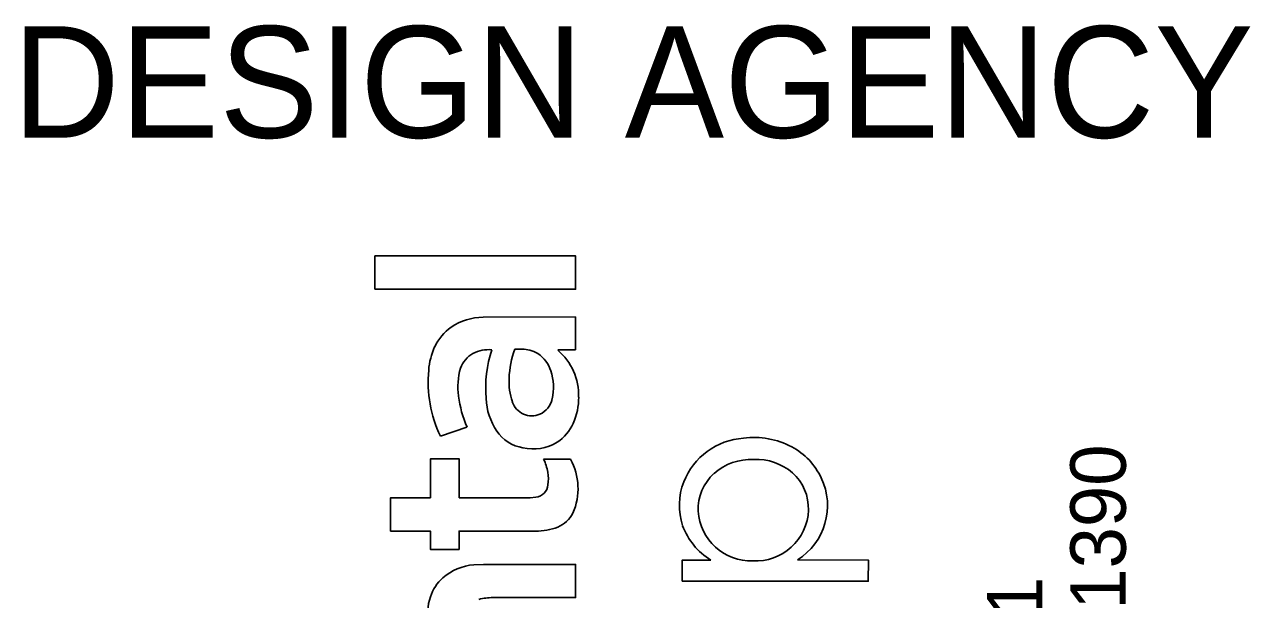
# Model space of a CAD drawing. Extents: x -1.7 to 34, y -55.6 to 22.
# Drawn here: x 32.061 to 33.162, y 4.436 to 4.951 of the extents above; entities that cross this region are included whole.
import ezdxf

# ---------------------------------------------------------------- set-up
doc = ezdxf.new("R2010")
doc.units = 0
doc.layers.add('SH_Data', color=7, linetype='Continuous')

msp = doc.modelspace()

# ---------------------------------------------------------------- linework, layer by layer
at = {"layer": 'SH_Data'}
for p, q in [((32.3756, 4.7141), (32.3756, 4.744)), ((32.3756, 4.744), (32.5557, 4.744)), ((32.5557, 4.744), (32.5557, 4.7141)), ((32.5557, 4.7141), (32.3756, 4.7141)), ((32.4727, 4.689), (32.5555, 4.6892)), ((32.5555, 4.6892), (32.5557, 4.6596)), ((32.5557, 4.6596), (32.5397, 4.6596)), ((32.4582, 4.5904), (32.4343, 4.5823)), ((32.4254, 4.527), (32.4255, 4.5621)), ((32.4255, 4.5621), (32.4511, 4.5621)), ((32.4511, 4.5621), (32.4512, 4.527)), ((32.527, 4.5616), (32.5511, 4.5616)), ((32.3896, 4.4972), (32.3896, 4.527)), ((32.3896, 4.527), (32.4254, 4.527)), ((32.4512, 4.527), (32.515, 4.527)), ((32.515, 4.527), (32.52, 4.5275)), ((32.4254, 4.4972), (32.3896, 4.4972)), ((32.4254, 4.4807), (32.4254, 4.4972)), ((32.5197, 4.4972), (32.4511, 4.4972)), ((32.4511, 4.4972), (32.4511, 4.4807)), ((32.4511, 4.4807), (32.4254, 4.4807)), ((32.6515, 4.4521), (32.6515, 4.4711)), ((32.6515, 4.4711), (32.6771, 4.4711)), ((32.7549, 4.4713), (32.8186, 4.4711)), ((32.8186, 4.4711), (32.8184, 4.4521)), ((32.4644, 4.4669), (32.4729, 4.4673)), ((32.4729, 4.4673), (32.5557, 4.4673)), ((32.5557, 4.4673), (32.5557, 4.4375)), ((32.8184, 4.4521), (32.6515, 4.4521)), ((32.5557, 4.4375), (32.4814, 4.4375))]:
    msp.add_line(p, q, dxfattribs=at)
msp.add_lwpolyline([(32.3756, 4.7141), (32.3756, 4.744), (32.5557, 4.744), (32.5557, 4.7141)], close=True, dxfattribs=at)
for points in [[(32.4727, 4.689), (32.5555, 4.6892), (32.5557, 4.6596)], [(32.5557, 4.6596), (32.5397, 4.6596)], [(32.4582, 4.5904), (32.4343, 4.5823)], [(32.5197, 4.4972), (32.4511, 4.4972), (32.4511, 4.4807), (32.4254, 4.4807), (32.4254, 4.4972), (32.3896, 4.4972), (32.3896, 4.527), (32.4254, 4.527), (32.4255, 4.5621), (32.4511, 4.5621), (32.4512, 4.527), (32.515, 4.527), (32.52, 4.5275)], [(32.527, 4.5616), (32.5511, 4.5616)], [(32.7549, 4.4713), (32.8186, 4.4711), (32.8184, 4.4521), (32.6515, 4.4521)], [(32.6515, 4.4521), (32.6515, 4.4711), (32.6771, 4.4711)], [(32.4644, 4.4669), (32.4729, 4.4673), (32.5557, 4.4673), (32.5557, 4.4375), (32.4814, 4.4375)]]:
    msp.add_lwpolyline(points, dxfattribs=at)
for centre, radius, start, end in [((32.4745, 4.6326), 0.0565, 91.8942, 122.6317), ((32.4745, 4.6326), 0.0565, 91.8942, 122.6317), ((32.4685, 4.6447), 0.043, 124.537, 155.6594), ((32.4685, 4.6447), 0.043, 124.537, 155.6594), ((32.4882, 4.6361), 0.0646, 155.9764, 175.3149), ((32.4882, 4.6361), 0.0646, 155.9764, 175.3149), ((32.4753, 4.6356), 0.024, 119.4252, 161.6629), ((32.4753, 4.6356), 0.024, 119.4252, 161.6629), ((32.4779, 4.6278), 0.0321, 85.3802, 116.6222), ((32.4779, 4.6278), 0.0321, 85.3802, 116.6222), ((32.5879, 4.6251), 0.1129, 162.0821, 184.5285), ((32.5879, 4.6251), 0.1129, 162.0821, 184.5285), ((32.5801, 4.6313), 0.0841, 159.8366, 178.0362), ((32.5801, 4.6313), 0.0841, 159.8366, 178.0362), ((32.5051, 4.6074), 0.053, 79.6696, 94.2322), ((32.5051, 4.6074), 0.053, 79.6696, 94.2322), ((32.5089, 4.6364), 0.0238, 56.8913, 76.2149), ((32.5089, 4.6364), 0.0238, 56.8913, 76.2149), ((32.5052, 4.6318), 0.0297, 17.5984, 55.7282), ((32.5052, 4.6318), 0.0297, 17.5984, 55.7282), ((32.5055, 4.6191), 0.0529, 358.0746, 49.762), ((32.5055, 4.6191), 0.0529, 358.0746, 49.762), ((32.5364, 4.6308), 0.113, 174.6101, 205.3899), ((32.5364, 4.6308), 0.113, 174.6101, 205.3899), ((32.5076, 4.6265), 0.0576, 163.1369, 188.1675), ((32.5076, 4.6265), 0.0576, 163.1369, 188.1675), ((32.5466, 4.6303), 0.0506, 175.5903, 199.8857), ((32.5466, 4.6303), 0.0506, 175.5903, 199.8857), ((32.4916, 4.6264), 0.0443, 345.9408, 18.9919), ((32.4916, 4.6264), 0.0443, 345.9408, 18.9919), ((32.5473, 4.6297), 0.0973, 186.7598, 203.7981), ((32.5473, 4.6297), 0.0973, 186.7598, 203.7981), ((32.5328, 4.6187), 0.0575, 182.5676, 213.7144), ((32.5328, 4.6187), 0.0575, 182.5676, 213.7144), ((32.5164, 4.6189), 0.0184, 198.2844, 293.3081), ((32.5164, 4.6189), 0.0184, 198.2844, 293.3081), ((32.5152, 4.6199), 0.0199, 295.2883, 347.4639), ((32.5152, 4.6199), 0.0199, 295.2883, 347.4639), ((32.5019, 4.6168), 0.0566, 336.016, 0.5951), ((32.5019, 4.6168), 0.0566, 336.016, 0.5951), ((32.5175, 4.6097), 0.0394, 303.4436, 336.18), ((32.5175, 4.6097), 0.0394, 303.4436, 336.18), ((32.5149, 4.6078), 0.0366, 215.0668, 259.8133), ((32.5149, 4.6078), 0.0366, 215.0668, 259.8133), ((32.7108, 4.5182), 0.0624, 93.9866, 158.3119), ((32.7108, 4.5182), 0.0624, 93.9866, 158.3119), ((32.7156, 4.5065), 0.0746, 62.6889, 97.0135), ((32.7156, 4.5065), 0.0746, 62.6889, 97.0135), ((32.5175, 4.6131), 0.0423, 257.5256, 300.882), ((32.5175, 4.6131), 0.0423, 257.5256, 300.882), ((32.7212, 4.5191), 0.0608, 25.0657, 61.9602), ((32.7212, 4.5191), 0.0608, 25.0657, 61.9602), ((32.4863, 4.542), 0.0452, 10.1545, 25.723), ((32.4863, 4.542), 0.0452, 10.1545, 25.723), ((32.503, 4.5351), 0.0549, 336.589, 28.8991), ((32.503, 4.5351), 0.0549, 336.589, 28.8991), ((32.7138, 4.5102), 0.0513, 87.8965, 131.1812), ((32.7138, 4.5102), 0.0513, 87.8965, 131.1812), ((32.7175, 4.5102), 0.0513, 49.9089, 92.0363), ((32.7175, 4.5102), 0.0513, 49.9089, 92.0363), ((32.4957, 4.5436), 0.0356, 351.914, 10.2059), ((32.4957, 4.5436), 0.0356, 351.914, 10.2059), ((32.7092, 4.5167), 0.0434, 132.3289, 182.0949), ((32.7092, 4.5167), 0.0434, 132.3289, 182.0949), ((32.7215, 4.5173), 0.0433, 358.0487, 47.9447), ((32.7215, 4.5173), 0.0433, 358.0487, 47.9447), ((32.5184, 4.54), 0.0126, 277.6142, 353.7918), ((32.5184, 4.54), 0.0126, 277.6142, 353.7918), ((32.707, 4.5202), 0.0581, 158.656, 198.171), ((32.707, 4.5202), 0.0581, 158.656, 198.171), ((32.7245, 4.52), 0.0574, 301.9776, 25.6418), ((32.7245, 4.52), 0.0574, 301.9776, 25.6418), ((32.5291, 4.5261), 0.0275, 292.6889, 332.0598), ((32.5291, 4.5261), 0.0275, 292.6889, 332.0598), ((32.7135, 4.5181), 0.0478, 183.5974, 271.7045), ((32.7135, 4.5181), 0.0478, 183.5974, 271.7045), ((32.7172, 4.518), 0.0477, 267.3149, 357.4019), ((32.7172, 4.518), 0.0477, 267.3149, 357.4019), ((32.7103, 4.5243), 0.0627, 200.8399, 238.0162), ((32.7103, 4.5243), 0.0627, 200.8399, 238.0162), ((32.5209, 4.5486), 0.0514, 268.6727, 291.5235), ((32.5209, 4.5486), 0.0514, 268.6727, 291.5235), ((32.4687, 4.4172), 0.0499, 94.9706, 130.2248), ((32.4687, 4.4172), 0.0499, 94.9706, 130.2248), ((32.4635, 4.4255), 0.0402, 132.2238, 161.6823), ((32.4635, 4.4255), 0.0402, 132.2238, 161.6823), ((32.4787, 4.4211), 0.056, 162.274, 187.7917), ((32.4787, 4.4211), 0.056, 162.274, 187.7917), ((32.4811, 4.3915), 0.046, 89.6051, 105.3303), ((32.4811, 4.3915), 0.046, 89.6051, 105.3303)]:
    msp.add_arc(centre, radius, start, end, dxfattribs=at)

# ---------------------------------------------------------------- texts
msp.add_text('DESIGN AGENCY', height=0.1, dxfattribs=at).set_placement((32.05, 4.85))
for s, p in [('800.835.1390', (33.0497, 4.1671)), ('450 GRANT ST., AKRON, OH  44311', (32.9749, 3.3374))]:
    msp.add_text(s, height=0.049846, rotation=90, dxfattribs=at).set_placement(p)

doc.saveas('drawing.dxf')
